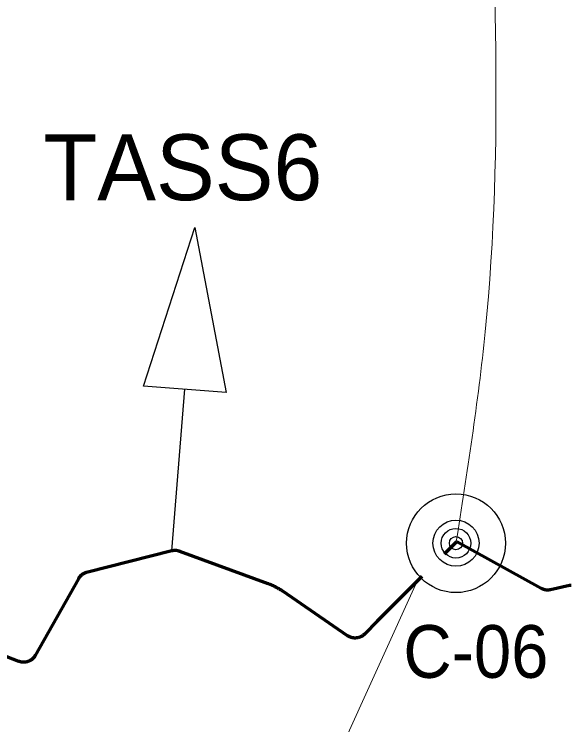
# Model space of a CAD drawing. Extents: x -1643653 to 4543381, y 1624270 to 13878484.
# Drawn here: x 618671 to 622897, y 8964597 to 8969992 of the extents above; entities that cross this region are included whole.
import ezdxf
from ezdxf.enums import TextEntityAlignment as Align

# ---------------------------------------------------------------- set-up
doc = ezdxf.new("R2010")
doc.units = 0
doc.header["$LTSCALE"] = 160
doc.linetypes.add('MEDIUM_DASHED', pattern=[4.5, 3, -1.5])
for name, color, linetype, lineweight in [('15', 7, 'Continuous', 25), ('50', 7, 'Continuous', 13), ('54', 7, 'Continuous', 25), ('60', 7, 'Continuous', 13), ('61', 7, 'Continuous', 70)]:
    doc.layers.add(name, color=color, linetype=linetype, lineweight=lineweight)

msp = doc.modelspace()

# ---------------------------------------------------------------- linework, layer by layer
at = {"layer": '15'}
for radius in [375, 175, 112.5, 50]:
    msp.add_circle((622025.5, 8965975.9), radius, dxfattribs=at)
at = {"layer": '50'}
msp.add_lwpolyline([(621730.8, 8965687.7), (619672.9, 8961158.9), (622869.9, 8961158.9)], dxfattribs=at)
msp.add_spline([(622025.5, 8965975.9), (622247.4, 8967581.3), (622247.4, 8971870.8)], degree=3, dxfattribs=at)
at = {"layer": '54'}
msp.add_line((619869, 8965917.2), (619966.8, 8967144.4), dxfattribs=at)
msp.add_lwpolyline([(619652, 8967169.5), (620042.3, 8968373.4), (620281.5, 8967119.3)], close=True, dxfattribs=at)
at = {"layer": '60', "lineweight": 25}
msp.add_spline([(814781, 9009175.5), (814787.2, 9009173.4), (814796.9, 9009173.4), (814799.4, 9009172.4), (814805.1, 9009174.5), (814805.6, 9009176.5), (814811.7, 9009179.5), (814811.7, 9009179.5), (814801.5, 9009181), (814790.7, 9009181.5), (814784.1, 9009183.1), (814777.4, 9009185.1), (814778.4, 9009175.5)], degree=3, dxfattribs=at)
at = {"layer": '61', "linetype": 'MEDIUM_DASHED'}
msp.add_line((621430.6, 8965386.2), (622031.1, 8965989.3), dxfattribs=at)
at = {"layer": '61'}
for points in [[(622031.1, 8965989.3), (622672.2, 8965634.7), (622674.7, 8965633.4), (622677.2, 8965632.1), (622679.8, 8965631), (622682.4, 8965629.8), (622685, 8965628.8), (622687.7, 8965627.8), (622690.4, 8965626.9), (622693.1, 8965626.1), (622695.8, 8965625.4), (622698.6, 8965624.7), (622701.3, 8965624.1), (622704.1, 8965623.6), (622706.9, 8965623.2), (622709.7, 8965622.8), (622712.5, 8965622.6), (622715.3, 8965622.4), (622718.2, 8965622.3), (622721, 8965622.2), (622723.8, 8965622.3), (622726.7, 8965622.4), (622729.5, 8965622.6), (622732.3, 8965622.9), (622735.1, 8965623.3), (622737.9, 8965623.8), (622740.7, 8965624.3), (622742.1, 8965624.6), (622888.8, 8965656.9), (622891.6, 8965657.5), (622894.4, 8965658), (622897.2, 8965658.4), (622900, 8965658.7)], [(620672.5, 8965634.3), (620667, 8965637.4), (620661.4, 8965640.4), (620655.8, 8965643.3), (620650.2, 8965646.2), (620644.5, 8965649), (620638.8, 8965651.7), (620633, 8965654.3), (620627.2, 8965656.8), (620621.4, 8965659.3), (620615.6, 8965661.8), (620609.7, 8965664.1), (620603.8, 8965666.4), (620599.8, 8965667.8), (619927.8, 8965914.1), (619925.2, 8965915.1), (619922.5, 8965915.9), (619919.7, 8965916.7), (619917, 8965917.4), (619914.2, 8965918.1), (619911.5, 8965918.6), (619908.7, 8965919.1), (619905.9, 8965919.5), (619903.1, 8965919.8), (619900.2, 8965920), (619897.4, 8965920.2), (619894.6, 8965920.2), (619891.8, 8965920.2), (619888.9, 8965920.2), (619886.1, 8965920), (619883.3, 8965919.7), (619880.5, 8965919.4), (619877.7, 8965919), (619874.9, 8965918.5), (619872.1, 8965918), (619869.4, 8965917.3), (619869, 8965917.2), (619220.9, 8965753.9), (619218.1, 8965753.2), (619215.4, 8965752.4), (619212.7, 8965751.5), (619210.1, 8965750.6), (619207.4, 8965749.5), (619204.8, 8965748.4), (619202.3, 8965747.2), (619199.7, 8965746), (619197.2, 8965744.7), (619194.8, 8965743.3), (619192.3, 8965741.8), (619190, 8965740.3), (619187.6, 8965738.7), (619185.3, 8965737), (619183.1, 8965735.3), (619180.9, 8965733.5), (619178.8, 8965731.6), (619176.7, 8965729.7), (619174.7, 8965727.8), (619172.7, 8965725.7), (619170.8, 8965723.6), (619168.9, 8965721.5), (619167.1, 8965719.3), (619165.4, 8965717.1), (619163.7, 8965714.8), (619162.1, 8965712.5), (619160.6, 8965710.1), (619159.1, 8965707.7), (619158.2, 8965706), (618829.8, 8965123.2), (618828.3, 8965120.7), (618826.9, 8965118.3), (618825.3, 8965116), (618823.7, 8965113.6), (618822, 8965111.4), (618820.2, 8965109.2), (618818.4, 8965107), (618816.5, 8965104.9), (618814.6, 8965102.8), (618812.6, 8965100.8), (618810.6, 8965098.8), (618808.5, 8965097), (618806.3, 8965095.1), (618804.1, 8965093.4), (618801.8, 8965091.7), (618799.5, 8965090), (618797.2, 8965088.4), (618794.8, 8965086.9), (618792.4, 8965085.5), (618789.9, 8965084.1), (618787.4, 8965082.8), (618784.8, 8965081.6), (618782.2, 8965080.4), (618779.6, 8965079.3), (618777, 8965078.3), (618774.3, 8965077.4), (618771.6, 8965076.5), (618768.9, 8965075.8), (618766.2, 8965075.1), (618763.4, 8965074.4), (618760.6, 8965073.9), (618757.8, 8965073.4), (618755.1, 8965073)], [(621430.6, 8965386.2), (621330.2, 8965285.5), (621328.2, 8965283.5), (621326.1, 8965281.6), (621324, 8965279.7), (621321.8, 8965277.9), (621319.6, 8965276.2), (621317.3, 8965274.5), (621315, 8965272.9), (621312.6, 8965271.4), (621310.2, 8965269.9), (621307.7, 8965268.5), (621305.2, 8965267.2), (621302.7, 8965266), (621300.1, 8965264.8), (621297.5, 8965263.7), (621294.9, 8965262.6), (621292.2, 8965261.7), (621289.6, 8965260.8), (621286.8, 8965260), (621284.1, 8965259.2), (621281.3, 8965258.6), (621278.6, 8965258), (621275.8, 8965257.5), (621273, 8965257.1), (621270.2, 8965256.7), (621267.4, 8965256.5), (621264.6, 8965256.3), (621261.7, 8965256.2), (621258.9, 8965256.1), (621256.1, 8965256.2), (621253.2, 8965256.3), (621250.4, 8965256.6), (621247.6, 8965256.8), (621244.8, 8965257.2), (621242, 8965257.7), (621239.2, 8965258.2), (621236.5, 8965258.8), (621233.7, 8965259.5), (621231, 8965260.3), (621228.3, 8965261.1), (621225.7, 8965262), (621223, 8965263), (621220.4, 8965264.1), (621217.8, 8965265.2), (621215.2, 8965266.5), (621212.7, 8965267.8), (621210.2, 8965269.1), (621207.8, 8965270.5), (621205.4, 8965272), (621203, 8965273.6), (621203, 8965273.6), (620710.1, 8965611), (620704.9, 8965614.5), (620699.6, 8965618), (620694.3, 8965621.4), (620688.9, 8965624.8), (620683.5, 8965628), (620678, 8965631.2), (620672.5, 8965634.3)], [(618755.1, 8965073), (618752.2, 8965072.7), (618749.4, 8965072.5), (618746.6, 8965072.3), (618743.8, 8965072.3), (618740.9, 8965072.3), (618738.1, 8965072.3), (618735.3, 8965072.5), (618732.5, 8965072.8), (618729.7, 8965073.1), (618726.9, 8965073.5), (618724.1, 8965074), (618721.3, 8965074.6), (618718.6, 8965075.2), (618715.8, 8965075.9), (618713.1, 8965076.7), (618710.4, 8965077.6), (618707.8, 8965078.5), (618707.1, 8965078.8), (618707.1, 8965078.8), (618404.7, 8965193.7)]]:
    msp.add_lwpolyline(points, dxfattribs=at)

# ---------------------------------------------------------------- texts
at = {"layer": '15', "width": 0.95}
msp.add_text('C-06', height=400, dxfattribs=at).set_placement((621625.8, 8964954.1))
at = {"layer": '54'}
msp.add_text('TASS6', height=500, dxfattribs=at).set_placement((619951.9, 8968580.2), align=Align.CENTER)

doc.saveas('drawing.dxf')
